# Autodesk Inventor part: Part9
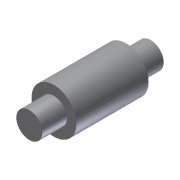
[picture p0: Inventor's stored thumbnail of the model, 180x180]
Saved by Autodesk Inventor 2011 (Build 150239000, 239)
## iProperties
Shininess: 77.0
Length Units: 11269
Angle Units: 11279
Time Units: 11290
Mass Units: 11283
Length Display Precision: 3
Angle Display Precision: 2
Created: 2002-01
Part Number: Part9
Document SubType Name: Modeling
Designer: ***
Density: 1 g/cm^3
Density: 0.0
Volumn: 0.0
Area: 0.0
PropertySet Name: Model Information
Control State: 0
Master: False
Checked Out: False
Author: ***
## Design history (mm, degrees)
sketch "Sketch1"
  geometry: L1 (0.279, 23.245)-(5.19, 23.245); L2 (5.19, 23.245)-(5.19, 13.947); L3 (5.19, 13.947)-(8.761, 13.947); L4 (8.761, 13.947)-(8.761, -13.295); L5 (8.761, -13.295)-(5.19, -13.295); L6 (5.19, -13.295)-(5.19, -22.592); L7 (5.19, -22.592)-(0.279, -22.592); L8 (0.279, -22.592)-(0.279, 23.245)
  constraints: 16 end point, 5 parallel, 2 equal length, 1 collinear, 1 horizontal, 1 perpendicular
revolve "Revolution1" sketch "Sketch1" stored, may be unused: angle "d0" = 90 deg
body "Solid1"
